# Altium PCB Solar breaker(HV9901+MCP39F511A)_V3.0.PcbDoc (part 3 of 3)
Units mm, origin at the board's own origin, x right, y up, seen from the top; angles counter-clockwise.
Board outline 92.89 x 56.75 mm, 4 copper layers (Component Side, Layer 2, Layer 3, Solder Side), stack 0.466 mm thick; 133 components, 95 nets, 366 pads, 141 vias.
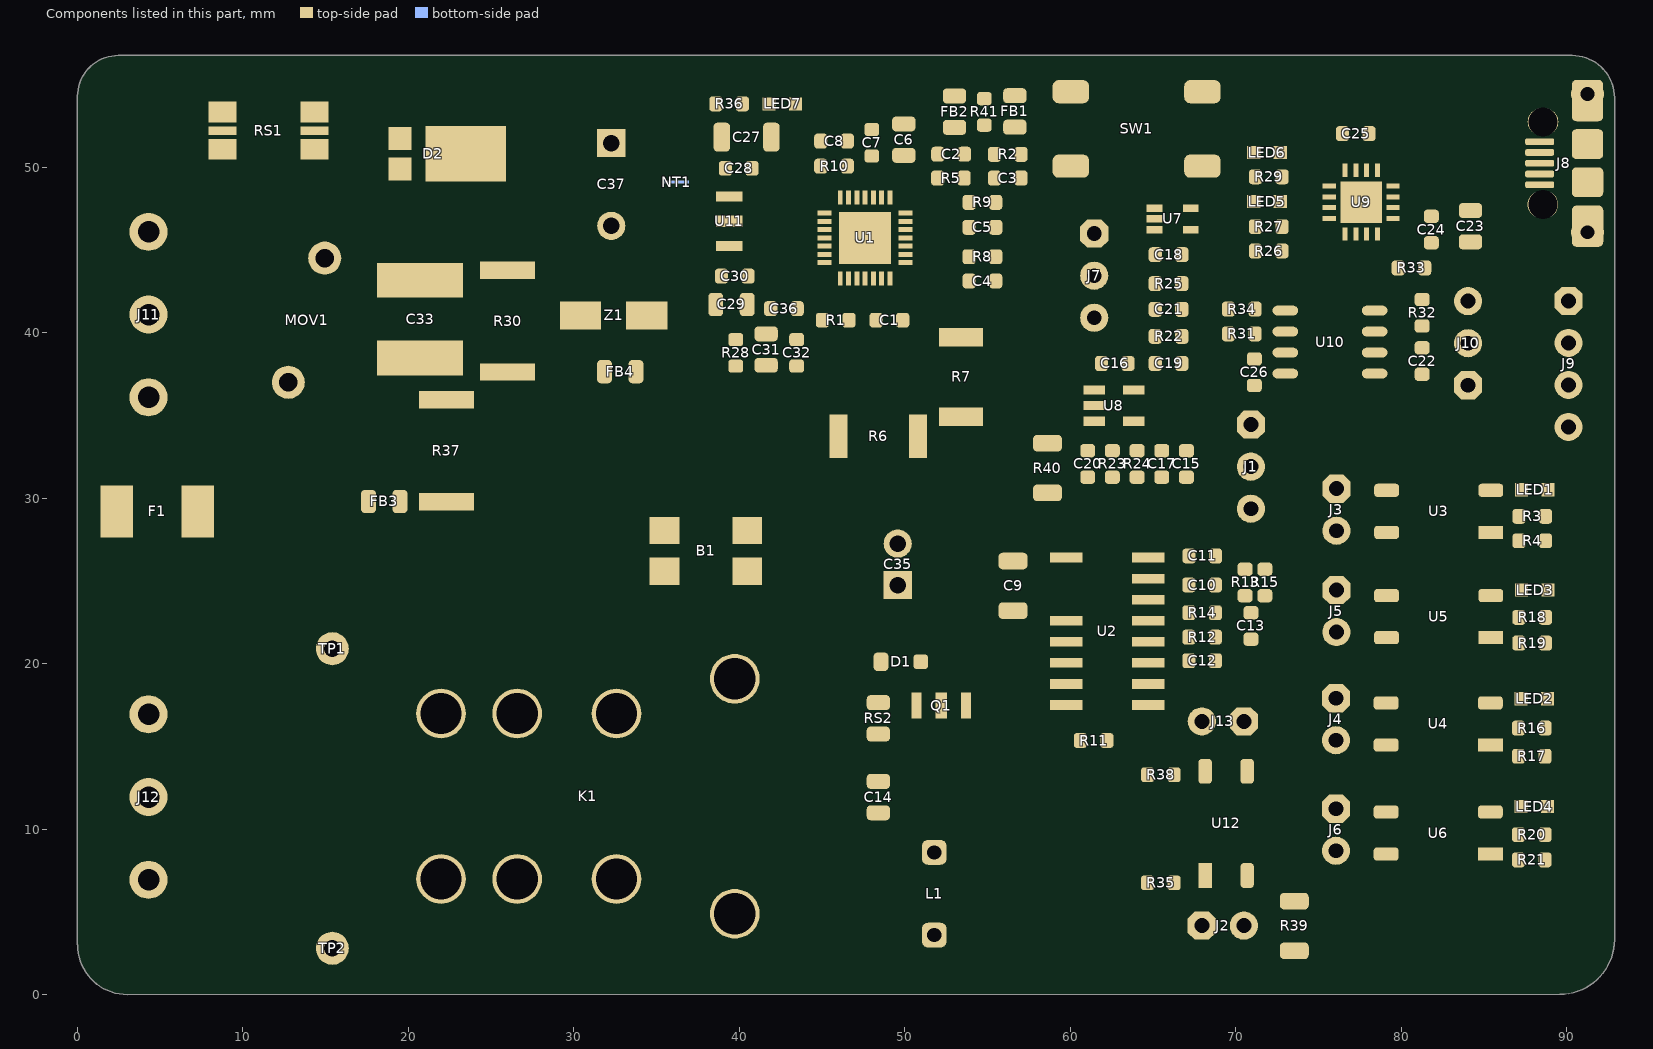
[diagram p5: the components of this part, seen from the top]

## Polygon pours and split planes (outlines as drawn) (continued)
no net on Component Side "Component Side-No Net 3" (solid, pour order 742): 63.218,36.367
no net on Component Side "Component Side-No Net 1" (solid, pour order 722): 32.829,26.67
no net on Component Side "Component Side-No Net 2" (solid, pour order 712): 378.551,40.248
no net on Component Side "NETC3_2" (solid, pour order 690): 42.118,41.086
no net on Component Side "NETC3_2" (solid, pour order 658): 41.407,41.975
no net on Component Side "NETC3_2" (solid, pour order 656): 378.277,41.492
no net on Component Side "NETC3_2" (solid, pour order 650): 378.696,36.505
no net on Component Side "NETC3_2" (solid, pour order 646): 40.342,50.156
no net on Component Side "NETC3_2" (solid, pour order 634): 100.296,19.691
no net on Component Side "NETC3_2" (solid, pour order 628): 46.498,53.28
no net on Component Side "NETC3_2" (solid, pour order 596): 142.359,506.147
GND on Component Side "Component Side-No Net" (solid, shelved, pour order 396): 31.428,9.803 31.428,2.717 31.758,2.387 35.72,2.387 35.72,5.714 36.33,6.324 36.33,8.837 33.789,11.378 31.91,11.378
GND on Solder Side "Solder Side-GND 1" (solid, pour order 1118): 52.286,27.992 8.871,27.992 6.453,25.575 6.453,2.447 8.2,0.7 60,0.7 60.9,1.6 60.9,10.471 60.7,10.671 53.7,17.671 53.7,24 53.7,26.847
GNDB on Solder Side "Solder Side-GNDB" (solid, pour order 998): 73.685,28.829 73.685,7.874 75.133,6.426 75.133,6.325 75.286,6.172 75.286,1.369 75.365,1.369 76.073,0.66 90.576,0.66 90.983,0.254 90.983,0.305 92.329,1.651 92.329,31.496 91.364,32.461 90.5,32.461 90.348,32.614 81.382,32.614 75.641,38.354 75.641,42.266 73.787,44.12 70.751,44.12 70.129,44.741 70.129,48.032 69.546,48.616 59.106,48.616 57.988,47.498 57.988,37.347 52.544,31.902 41.845,31.902 40.132,33.616 40.132,36.678 36.017,40.792 36.017,54 36.017,55.245 35.027,56.236 23.002,56.236 1.778,56.236 0.432,54.889 0.432,44.78 1.302,43.91 6.179,43.91 8.458,41.631 15.496,41.631 25.324,31.799 28.98,28.143 53.391,28.143 53.873,28.626 55.042,29.794 56.439,29.794 56.836,30.191 56.836,31.588 57.15,31.902 60.249,31.902 60.554,31.598 60.554,30.353 61.163,29.743 67.589,29.743 68.438,29.743 69.509,30.814 69.509,35.092 70.129,35.712 71.679,35.712 72.309,35.082 72.309,30.205
GND on Solder Side "Solder Side-GND" (solid, pour order 1004): 61.951,2.438 64.151,0.238 71.987,0.238 73.206,1.458 73.206,28.849 72.566,29.489 71.986,30.069 71.986,32.595 71.536,33.045 70.18,33.045 69.774,32.639 69.774,30.632 68.631,29.489 55.27,29.489 54.116,28.335 54.116,19.671 61.951,11.836
no net on Solder Side "Solder Side-No Net 1" (solid, pour order 1002): 65.405,26.556
AGND on Solder Side "Solder Side-No Net 2" (solid, pour order 990): 36.292,55.26 36.292,41.204 40.335,37.16 40.335,33.744 42.03,32.05 52.319,32.05 57.725,37.455 57.725,47.83 58.708,48.813 69.084,48.813 69.85,49.579 69.85,55.27 68.885,56.236 56.109,56.236 37.336,56.236
GND-ISO on Solder Side "Solder Side-GND_ISO" (solid, pour order 788): 70.364,54.971 70.364,44.887 70.892,44.359 74.59,44.359 76.192,42.756 76.192,38.565 81.616,33.142 91.079,33.142 92.38,34.442 92.38,55.321 91.334,56.367 71.76,56.367
no net on Solder Side "Solder Side-No Net" (solid, pour order 896): 64.11,31.242
no net on Solder Side "NETC3_2" (solid, pour order 492): 107.242,25.462
no net on Solder Side "NETC3_2" (solid, pour order 473): 1034.966,-477.941
GNDB on Layer 2 "Layer 2-GNDB" (solid, pour order 982): 0.561,28.014 0.561,54.766 2.157,56.363 68.504,56.363 69.817,55.049 69.817,44.788 70.663,43.942 74.217,43.942 74.413,43.746 75.438,42.721 75.438,38.862 81.509,32.791 91.434,32.791 92.405,31.82 92.405,2.565 90.678,0.838 89.916,0.838 75.59,0.838 75.006,1.422 75.006,6.528 72.873,8.661 72.873,34.703 72.523,35.052 71.406,36.17 69.817,36.17 68.707,35.059 68.707,31.609 68.707,31.267 68.097,30.658 60.722,30.658 60.477,30.902 60.477,31.532 60.051,31.959 35.666,31.959 30.834,27.127 1.448,27.127
GND on Layer 2 "Layer 2-GND" (solid, pour order 980): 72.509,0.991 74.27,0.991 74.608,1.329 74.608,6.347 72.509,8.445 72.509,34.56 71.057,36.011 69.954,36.011 68.936,34.993 68.936,31.115 68.301,30.48 60.586,30.48 60.3,30.766 60.3,31.416 60.016,31.699 59.367,31.699 45.248,31.699 36.337,31.699 31.434,26.797 0.787,26.797 0.483,26.492 0.483,19.558 0.483,2.53 2.022,0.991
GND-ISO on Layer 2 "Layer 2-GND_ISO" (solid, pour order 748): 72.087,56.693 91.389,56.693 92.862,55.22 92.862,34.925 91.084,33.147 81.902,33.147 76.192,38.856 76.192,42.744 74.562,44.374 70.876,44.374 70.364,44.887 70.387,54.996
5VUSB on Layer 3 "Layer 3-5VUSB" (solid, pour order 1128): 72.729,45.06 73.5,44.289 73.5,42.41 80.71,35.2 81.32,35.2 81.66,35.54 81.66,37.412 80.285,38.787 79.428,38.787 78.1,40.115 78.1,44.272 78.805,44.977 85.099,44.977 87.782,42.293 89.105,40.971 91.378,40.971 92.604,42.197 92.604,54.741 91.211,56.134 71.552,56.134 70.434,55.016 70.434,47.355
3.3D on Layer 3 "Layer 3-3.3D" (solid, pour order 1124): 48.596,52.798 49.324,52.07 52.68,52.07 54.026,53.416 59.974,53.416 66.497,46.893 66.497,44.238 66.889,43.846 67.047,43.688 68.074,43.688 68.402,43.36 68.402,43.043 68.955,42.49 68.955,41.904 68.861,41.81 66.067,41.81 64.353,40.096 63.455,40.096 63.424,40.065 62.738,39.379 62.738,38.955 62.905,38.787 64.083,38.787 64.235,38.787 65.225,39.776 67.589,39.776 68.343,40.53 68.956,40.53 69.236,40.249 69.236,37.651 69.587,37.3 71.28,37.3 71.9,37.92 71.9,41.491 69.933,43.458 69.933,44.977 60.528,54.382 49.454,54.381 49.149,54.077 48.596,53.523
no net on Layer 3 "Layer 3-No Net 1" (solid, pour order 1120): 69.256,40.229
N-IN on Layer 3 "Layer 3-N-IN" (solid, pour order 1116): 14.025,45.714 15.831,45.714 34.4,27.145 34.4,18.881 34.4,15.932 33.8,15.332 31.059,15.332 30.9,15.49 30.379,16.012 30.379,25.921 13.3,43 13.3,44.989
Neutral on Layer 3 "Layer 3-Neutral" (solid, pour order 1114): 2.1,45.742 2.1,48.1 3.9,49.9 18.449,49.9 29.649,38.7 30.6,38.7 31.1,38.2 31.1,37.022 30.577,36.499 30.1,36.499 27.681,36.499 17.012,47.168 7.502,47.168 5.135,44.801 3.048,44.826
L-IN on Layer 3 "Layer 3-L-IN" (solid, pour order 1098): 34.6,4.766 34.6,10.1 31.169,13.531 14.469,13.531 12,16 12,23.761 14.439,26.2 14.439,38.079 13.717,38.8 11.9,38.8 10.769,37.67 10.769,28.231 8.769,26.23 8.769,13.531 11.9,10.4 29.1,10.4 30.6,8.9 30.6,4.728 31.734,3.594 33.428,3.594
GNDB on Layer 3 "Layer 3-GNDB 2" (solid, pour order 1006): 19.554,56.236 36.322,56.236 37.541,55.016 37.541,45.21 37.89,44.861 39.406,43.345 39.406,40.02 39.726,39.7 40.716,39.7 41.021,40.005 41.021,41.833 41.352,42.164 46.329,42.164 47.954,40.539 50.521,40.548 50.81,40.259 51.308,40.259 55.013,40.259 59.28,35.992 60.833,35.992 63.678,33.147 67.986,33.147 68.351,32.782 68.351,17.043 68.351,16.332 67.589,15.57 65.587,15.57 64.541,15.57 63.602,14.63 63.602,11.455 64.084,10.973 70.993,10.973 72.238,12.217 74.168,14.148 74.168,18.212 74.168,31.086 75.071,31.973 76.226,31.952 78.377,29.802 79.35,28.829 79.35,26.304 79.35,21.971 86.97,14.351 86.97,9.931 86.97,7.944 88.361,6.553 88.951,6.553 89.189,6.792 89.189,7.839 88.036,8.992 88.036,14.503 82.728,19.812 82.728,26.682 82.728,35.989 78.392,40.325 78.392,43.038 79.753,44.399 84.099,44.399 87.224,41.275 92.507,35.992 92.507,16.739 92.507,2.948 90.22,0.66 82.321,0.66 57.48,0.66 55.88,2.261 55.88,15.037 59.741,18.898 59.741,30.658 59.563,30.836 58.425,31.973 38.855,31.973 35.558,35.27 18.343,52.411 18.332,55.008
3.3D on Layer 3 "Layer 3-3.3D 1" (solid, pour order 1008): 39.675,40.313 39.675,43.612 37.981,45.306 37.981,53.348 39.522,54.889 45.441,54.889 47.12,53.21 47.12,52.632 46.66,52.172 46.152,52.172 44.856,53.467 40.742,53.467 39.522,52.248 39.522,45.801 40.843,44.48 40.843,43.891 40.844,41.046 40.844,40.189 40.609,39.954 40.034,39.954
GNDB on Layer 3 "Layer 3-GNDB" (solid, pour order 950): 39.776,45.796 39.776,52.121 40.754,53.099 44.884,53.099 45.745,52.237 45.745,50.8 43.536,48.59 43.536,47.818 43.536,47.473 42.774,46.711 42.774,44.78 42.227,44.234 41.339,44.234
GNDB on Layer 3 "Layer 3-GNDB 1" (solid, pour order 946): 46.025,47.396 49.225,47.396 49.225,44.12 46.66,44.12 46.025,44.755
VCC on Layer 3 "Layer 3-VCC" (solid, pour order 922): 73.431,14.529 73.431,33.609 71.633,35.408 70.155,35.408 68.936,34.188 68.936,28.081 68.936,15.702 68.271,15.037 64.578,15.037 64.045,14.596 64.045,11.703 64.255,11.493 64.445,11.303 67.702,11.303 70.206,11.303
no net on Layer 3 "Layer 3-No Net" (solid, pour order 820): 27.305,39.141

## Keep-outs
Keep-Out Layer:
  text ".Layer_Name" at 290.002,-112.792 h1.5

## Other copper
Layer 3:
  pour cut-out: 39.141,1.829

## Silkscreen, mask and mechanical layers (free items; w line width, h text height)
Top Overlay:
  circle w0.381: c78.454,36.5 r0.203
  lines w0.203: 36.623,53.85 36.626,52.539 ; 36.627,52.539 37.973,52.542 ; 37.973,52.959 37.981,49.393 ; 43.84,50.075 44.196,50.075 ; 49.2,54.915 51.638,54.915 51.638,51.714 ; 51.246,51.634 57.731,51.634 ; 51.263,48.587 57.721,48.556 ; 58.877,52.426 60.554,52.4 ; 64.222,41.338 64.516,41.338 ; 67.397,39.785 67.691,39.785 ; 44.454,53.438 44.454,56.308 49.2,56.308 49.2,53.438 44.454,53.438
  lines w0.254: 51.232,48.587 51.246,51.635 ; 57.722,48.641 57.725,49.288 ; 57.731,51.634 57.731,50.584 57.725,49.288 ; 60.423,5.081 60.423,7.418 ; 60.561,7.418 63.249,7.418 ; 66.407,27.458 66.369,19.427 72.668,19.397 72.706,27.434 ; 66.45,27.457 72.706,27.457 ; 67.361,1.295 68.072,1.295 68.072,2.718 ; 69.844,19.411 69.844,20.752 72.669,20.752 ; 70.561,2.667 70.561,1.295 71.317,1.295 ; 73.334,52.095 73.354,56.337 ; 73.508,53.795 73.926,53.793 73.882,44.558 ; 87.138,34.443 87.151,33.745 ; 87.154,33.745 88.621,33.745 ; 57.725,49.288 57.725,49.288 ; 57.059,4.934 57.059,13.514 63.356,13.514 63.356,4.934 57.059,4.934
  text "RESET" at 61.7,55.6 h1.4
  text "Inlet" at 1.981,52.268 h3.05
  text "1" at 63.068,45.695 h1.52
  text "TEMP OUT" at 57.556,45.212 h0.89
  text "N" at 8.636,45.11 h2.54
  text "ANALOG /          _IN" at 56.464,42.443 h0.89
  text "1" at 91.872,41.465 h1.52
  text "PWM" at 57.81,40.488 h0.89
  text "G" at 8.509,40.386 h2.54
  text "1" at 81.763,36.017 h1.52
  text "L" at 8.636,35.219 h2.54
  text "Ext.isolated / serial comm" at 88.316,34.747 h1.52 r90
  text "VCC" at 69.118,33.833 h1.4 r90
  text "" at 33,32.2 h8.89
  text "1" at 77.775,30.912 h1.52
  text "GND" at 69.063,30.861 h1.4 r90
  text "*h" at 25.414,29.277 h4.57
  text "-" at 39.7,29.05 h1
  text "EVENT1" at 74.346,28.902 h1.52 r90
  text "VDD" at 69.037,27.911 h1.4 r90
  text "Fast Blow" at 1.93,25.832 h1.52
  text "1" at 77.775,24.816 h1.52
  text "Solar breaker(HV9901+ / MCP39F511A)  V3.0" at 10.3,24.7 h2.16
  text "250VAC,1A" at 1.245,24.409 h1.52
  text "+" at 39.7,23.425 h1
  text "2020.6.19" at 23.1,23.3 h1.78
  text "ZCD" at 74.346,23.076 h1.52 r90
  text "K1-PIN3" at 8.7,21.2 h1.52
  text "A" at 71.095,19.634 h1.4
  text "5" at 31.9,19.2 h2.54
  text "1" at 21.386,19.172 h2.54
  text "3" at 25.8,19.172 h2.54
  text "1" at 77.775,18.39 h1.52
  text "ENI" at 67.056,18.212 h1.27
  text "GND" at 69.317,18.212 h1.27
  text "N" at 8.636,16.002 h2.54
  text "7" at 39.306,15.353 h2.54
  text "EVENT2" at 74.346,14.224 h1.52 r90
  text "1" at 77.775,11.735 h1.52
  text "G" at 8.509,10.922 h2.54
  text "8" at 39.1,7.112 h2.54
  text "PWM Output" at 74.295,6.553 h1.4 r90
  text "L" at 8.636,6.35 h2.54
  text "A" at 61.293,5.666 h1.78
  text "C" at 83.21,3.378 h3.81
  text "2" at 21.2,3.3 h2.54
  text "4" at 25.9,3.3 h2.54
  text "6" at 32.1,3.3 h2.54
  text "" at 80.442,3.124 h3.81
  text "" at 77.009,2.819 h3.81
  text "" at 86.919,2.388 h3.81
  text "" at 89.56,2.21 h3.81
  text "Outlet" at 1.168,1.651 h3.05
  text "EXT-MCU-IN" at 60.071,0.94 h1.27
  text "GND-EXT-MCU" at 71.552,0.94 h1.27
  text "K1-PIN4" at 9.4,0.8 h1.52
Top Paste:
  text ".ProjectRevisionART" at 325.18,-112.615 h1.5
  text ".Layer_Name" at 290.002,-112.792 h1.5
Bottom Paste:
  text ".ProjectRevisionART" at 325.18,-112.615 h1.5
  text ".Layer_Name" at 290.002,-112.792 h1.5
NOTES (M1):
  lines w0.051: 36.751,12.112 ccw(c36.795,12.232) 36.795,12.104 ; 37.538,56.877 cw(c37.543,56.75) 37.543,56.877 cw(c37.543,54.191) 37.564,56.877 ; 37.564,56.877 cw(c37.543,54.191) 37.574,56.877 ; 37.564,56.877 37.574,56.877 ; 37.564,56.877 37.569,56.877 cw(c37.569,56.75) 37.574,56.877
  lines w0.254: -0.232,61.746 -0.232,62.254 ; 2.768,61 -0.232,62 ; 2.768,63 -0.232,62 ; 34.559,62 -0.232,62 ; 57.864,62 92.655,62 ; 89.655,61 92.655,62 ; 89.655,63 92.655,62 ; 92.655,61.746 92.655,62.254 ; 99,3.021 100,0.021 ; 99,53.753 100,56.753 ; 99.746,0.021 100.254,0.021 ; 99.746,56.753 100.254,56.753 ; 100,16.734 100,0.021 ; 100,40.04 100,56.753 ; 101,3.021 100,0.021 ; 101,53.753 100,56.753
  text "92.886mm" at 34.813,60.348 h3
  text "56.733mm" at 101.652,16.988 h3 r90
  text ".Layer_Name" at 308.002,-112.792 h1.5
Route Tool Path:
  lines w0.254: 0,3.001 0,54.282 cw(c2.471,54.282) 2.471,56.752 ; 0.012,3.001 ccw(c3.013,3.001) 3.013,0 ; 2.547,56.75 90.404,56.75 ; 3.013,-0.001 89.58,0.011 ; 89.58,0.021 ccw(c89.58,3.327) 92.886,3.327 92.886,54.191 ccw(c90.328,54.191) 90.328,56.75
REF POINTS (M3):
  text ".Layer_Name" at 290.002,-112.792 h1.5
FAB (M4):
  lines w0.254: 249.419,73.357 251.959,75.897 ; 249.419,75.897 251.959,73.357 ; 320.158,58.934 321.682,58.934 ; 320.158,60.458 321.682,60.458 ; 320.92,59.696 320.92,61.22 ; 248.784,31.892 248.784,35.702 252.594,35.702 252.594,31.892 248.784,31.892 ; 248.784,37.502 252.594,37.502 252.594,41.312 248.784,41.312 248.784,37.502 ; 248.784,43.002 248.784,46.812 252.594,46.812 252.594,43.002 248.784,43.002 ; 248.784,48.282 252.594,48.282 252.594,52.092 248.784,52.092 248.784,48.282 ; 248.784,72.722 252.594,72.722 252.594,76.532 248.784,76.532 248.784,72.722 ; 259.024,-2.248 278.475,-2.248 278.475,1.562 259.024,1.562 259.024,-2.248 ; 269.104,23.152 269.104,26.962 332.604,26.962 332.604,23.152 269.104,23.152 ; 276.724,72.722 276.724,76.532 280.534,76.532 280.534,72.722 276.724,72.722 ; 279.264,10.452 279.264,14.262 332.604,14.262 332.604,10.452 279.264,10.452 ; 279.264,16.802 332.604,16.802 332.604,20.612 279.264,20.612 279.264,16.802 ; 299.475,53.282 299.475,57.092 303.285,57.092 303.285,53.282 299.475,53.282 ; 299.584,58.172 299.584,61.982 308.474,61.982 308.474,58.172 299.584,58.172 ; 299.584,63.022 299.584,66.832 308.474,66.832 308.474,63.022 299.584,63.022 ; 299.584,67.872 308.474,67.872 308.474,71.682 299.584,71.682 299.584,67.872 ; 299.584,72.722 299.584,76.532 303.394,76.532 303.394,72.722 299.584,72.722 ; 308.314,-2.248 308.314,1.562 325.475,1.562 325.475,-2.248 308.314,-2.248 ; 316.475,53.282 320.285,53.282 320.285,57.092 316.475,57.092 316.475,53.282 ; 322.444,58.172 331.334,58.172 331.334,61.982 322.444,61.982 322.444,58.172
  text "THIS PCB TO BE MANUFACTURED TO MEET ALL ACCEPTANCE LEVELS" at 228.464,86.518 h1.78
  text "OF A CLASS 2 PCB PER ANSI/IPC-A-600G." at 228.464,82.708 h1.78
  text "MATERIAL:" at 228.464,78.088 h1.78
  text "FR-4 or Equivalent" at 248.784,78.088 h1.78
  text "FINISH:" at 236.514,75.897 h1.78
  text "CONTROLLED IMPEDANCE" at 304.975,73.856 h1.78
  text "MULTILAYER" at 254.499,73.738 h1.78
  text "4" at 277.994,73.738 h1.78
  text "LAYERS" at 282.439,73.738 h1.78
  text "Cu WEIGHT EXTERNAL LAYERS" at 248.784,68.888 h1.78
  text "50um" at 300.854,68.888 h1.78
  text "FINISHED" at 310.379,68.888 h1.78
  text "Cu WEIGHT INTERNAL LAYERS" at 248.784,64.038 h1.78
  text "35um" at 300.854,64.038 h1.78
  text "FINISHED" at 310.379,64.038 h1.78
  text "FINISHED OVERALL THICKNESS" at 248.784,59.188 h1.78
  text "1.6" at 302.124,59.188 h1.78
  text "mm" at 310.379,59.188 h1.78
  text "10" at 324.984,59.188 h1.78
  text "%" at 333.239,59.188 h1.78
  text "COPPER THIEVING ALLOWED" at 248.975,54.356 h1.78
  text "YES" at 305.975,54.356 h1.78
  text "NO" at 322.975,54.356 h1.78
  text "X" at 317.566,53.856 h2.6
  text "LEAD-FREE HOT AIR LEVELING" at 254.475,49.556 h1.78
  text "X" at 249.875,48.856 h2.6
  text "IMMERSION GOLD" at 254.499,44.018 h1.78
  text "IMMERSION TIN" at 254.499,38.518 h1.78
  text "SMOBC WITH SELECTIVE GOLD PLATING ON LANDS" at 254.499,34.813 h1.78
  text "INDICATED. 1um GOLD OVER 5-10 um NICKEL" at 254.499,31.003 h1.78
  text "SOLDERMASK" at 248.784,24.168 h1.78
  text "DYNACHEM EPIC 200 LPI OR EQUIVALENT" at 270.374,24.168 h1.78
  text "SOLDERMASK COLOR" at 248.784,17.818 h1.78
  text "GREEN HIGH GLOSS" at 280.534,17.818 h1.78
  text "SILKSCREEN COLOR" at 248.784,11.468 h1.78
  text "WHITE" at 280.534,11.468 h1.78
  text "ALL HOLES TO BE LOCATED BY THE COORDINATES FROM THE NC DRILL DATA PROVIDED." at 228.464,5.118 h1.78
  text "05-" at 260.475,-1.144 h1.78
  text ".ProjectBoardNumber" at 265.475,-1.144 h1.78
  text "PCB REV" at 296.475,-1.144 h1.78
  text "USE ARTWORK SET NO." at 228.464,-1.232 h1.78
  text ".ProjectRevisionART" at 309.625,-1.394 h1.78
  text "ALL UL LOGO, MANUFACTURER'S ID, AND DATE CODES SHALL BE PLACED" at 228.464,-7.582 h1.78
  text "ON THE BOTTOM SIDE UNLESS OTHERWISE INDICATED." at 228.464,-11.392 h1.78
  text "ANY ALTERNATIVES TO THE ABOVE SPECIFICATIONS MUST FIRST BE APPROVED." at 227.975,-16.644 h1.78
  text ".ProjectRevisionFAB" at 325.18,-112.615 h1.5
  text ".Layer_Name" at 290.002,-112.792 h1.5
Case (M5):
  text ".Layer_Name" at 290.002,-112.792 h1.5
Cover (M6):
  text ".Layer_Name" at 290.002,-112.792 h1.5
Terminal Block (M7):
  text ".Layer_Name" at 290.002,-112.792 h1.5
Milling (M8):
  text ".Layer_Name" at 290.002,-112.792 h1.5
V-Cut (M9):
  text ".Layer_Name" at 290.002,-112.792 h1.5
Assy BOT (M10):
  text ".variantName" at 39.572,-96.792 h0.9
  text "ASSEMBLY VARIANT:" at 53.822,-96.792 h0.9
  text "DOCUMENT NUMBER:" at 7.552,-105.042 h1.14
  text "-D" at -6.448,-108.042 h1.78
  text ".ProjectBoardNumber" at 1.802,-108.042 h1.78
  text "02-" at 7.302,-108.042 h1.78
  text ".ProjectRevisionASSY" at -9.375,-112.615 h1.5
  text ".Layer_Name" at 25.502,-112.792 h1.5
Assy TOP (M11):
  text "ASSEMBLY NOTES:" at -5.948,-63.286 h4
  text "1. ALL COMPONENTS SHALL BE RoHS COMPLIANT." at -15.198,-68.242 h3
  text "2. ALL UNUSED THROUGH HOLE COMPONENT LOCATIONS SHALL BE FREE OF SOLDER." at -15.198,-71.242 h3
  text "3. ALL COMPONENTS SHALL BE MOUNTED FLUSH TO THE BOARD, EXCEPT AS NOTED." at -15.198,-74.242 h3
  text "4. FINISHED BOARD SHALL BE FREE OF ALL RESIDUES." at -15.198,-77.242 h3
  text "5. ALL LEADS SHALL BE TRIMMED TO A MAXIMUM HEIGHT OF 2mm" at -15.198,-80.242 h3
  text "6. PLACE LABEL  ON THE LOCATION INDICATED." at -15.198,-83.242 h3
  text "7." at -15.198,-86.242 h3
3D BOT (M12):
  text ".Layer_Name" at 290.002,-112.792 h1.5
3D TOP (M13):
  text ".Layer_Name" at 290.002,-112.792 h1.5
TITLE (M16):
  lines w0.1: 261.502,-95.542 343.322,-95.542 ; 318.502,-88.042 318.502,-91.042 343.322,-91.042 ; 332.042,-112.677 332.042,-111.407 ; 332.042,-112.042 342.202,-112.042 ; 332.202,-110.842 332.202,-109.842 ; 332.202,-110.342 342.202,-110.342 ; 334.582,-112.677 334.582,-111.407 ; 337.122,-112.677 337.122,-111.407 ; 337.202,-110.642 337.202,-110.042 ; 339.662,-112.677 339.662,-111.407 ; 342.202,-112.677 342.202,-111.407 ; 342.202,-110.842 342.202,-109.842 ; 343.322,-91.042 343.322,-91.042
  lines w0.127: -32.598,-58.217 -27.518,-58.217 ; -32.598,62.433 -27.518,62.433 ; -32.443,9.839 -27.363,9.839 ; 30.902,-118.542 30.902,-113.462 ; 94.402,-118.542 94.402,-113.462 ; 157.902,-118.542 157.902,-113.462 ; 157.902,117.678 157.902,122.758 ; 193.462,-113.462 229.022,-113.462 ; 221.402,-118.542 221.402,-113.462 ; 221.402,117.678 221.402,122.758 ; 227.502,-113.462 227.502,-88.042 343.322,-88.042 ; 261.502,-113.462 261.502,-88.042 ; 261.502,-109.042 343.322,-109.042 ; 261.502,-103.042 343.322,-103.042 ; 261.502,-97.042 343.322,-97.042 ; 284.902,-118.542 284.902,-113.462 ; 284.902,117.678 284.902,122.758 ; 289.502,-113.462 289.502,-97.042 ; 307.502,-109.042 307.502,-103.042 ; 320.502,-113.462 320.502,-109.042 ; 328.002,-113.462 328.002,-103.042 ; 343.322,-82.982 343.322,-113.462 ; 343.322,-58.217 348.402,-58.217 ; 343.322,2.108 348.402,2.108 ; 343.322,-113.462 343.322,117.678 -27.518,117.678 -27.518,-113.462 343.322,-113.462 ; -32.598,-118.542 -32.598,122.758 348.402,122.758 348.402,-118.542 -32.598,-118.542
  lines w0.305: 221.502,117.458 221.502,112.958 ; 232.502,108.458 232.502,112.958 232.502,117.458 ; 245.002,108.458 245.002,112.958 245.002,117.458 ; 323.502,108.458 323.502,112.958 323.502,117.458 ; 343.002,108.458 221.502,108.458 221.502,112.958 ; 343.002,112.958 221.502,112.958
  text "4" at 188.967,119.456 h1.78
  text "5" at 252.441,119.456 h1.78
  text "6" at 316.068,119.456 h1.78
  text "REV" at 224.002,114.458 h0.76
  text "ECO" at 234.002,114.458 h0.76
  text "Comments" at 280.502,113.958 h0.76
  text "Date" at 328.502,113.958 h0.76
  text "A" at -31.089,98.622 h1.78
  text "A" at 345.227,90.424 h1.78
  text "B" at -30.693,29.972 h1.78
  text "B" at 345.227,29.972 h1.78
  text "C" at -30.693,-30.353 h1.78
  text "C" at 345.227,-30.353 h1.78
  text "PART NUMBER:" at 319.502,-90.042 h1
  text ".ProjectpartNumber" at 331.502,-90.292 h1.5
  text "TITLE:" at 262.502,-90.542 h1.14
  text "D" at -30.693,-90.551 h1.78
  text "D" at 345.227,-90.551 h1.78
  text ".ProjectTitle" at 262.502,-94.542 h2.5
  text "PCB DESIGNER:" at 262.502,-99.042 h1.14
  text "GERBER FILE:" at 290.502,-99.042 h1.14
  text ".ProjectDrawnBy" at 262.502,-102.042 h1.78
  text ".Plot_File_Name" at 290.502,-102.042 h1.5
  text "M" at 230.502,-104.042 h15.24
  text "ENGINEER:" at 262.502,-105.042 h1.14
  text "BOARD NUMBER:" at 290.502,-105.042 h1.14
  text "DATE:" at 329.202,-105.042 h1.14
  text "Microchip Technology Inc." at 229.272,-107.302 h1.78
  text ".ProjectBoardNumber" at 295.245,-108.017 h1.78
  text ".ProjectEngineer" at 262.502,-108.042 h1.78
  text "04-" at 290.502,-108.042 h1.78
  text ".PRINT_DATE" at 329.202,-108.042 h1.5
  text "2355 W. Chandler Blvd." at 230.502,-110.042 h1.78
  text "LAYER NAME:" at 290.502,-110.542 h1.14
  text "10mm" at 328.502,-110.642 h0.7
  text "PCB FILE NAME:" at 262.502,-110.792 h1.14
  text "REV:" at 321.252,-110.792 h1.14
  text "400mil" at 328.402,-112.342 h0.7
  text "Chandler, AZ  85224" at 231.502,-112.542 h1.78
  text ".PCB_FILE_NAME_NO_PATH" at 262.502,-112.792 h1.14
  text "1" at -1.322,-116.764 h1.78
  text "2" at 62.068,-116.764 h1.78
  text "3" at 125.298,-116.764 h1.78
  text "4" at 188.967,-116.764 h1.78
  text "5" at 252.441,-116.764 h1.78
  text "6" at 316.068,-116.764 h1.78
Drill Drawing:
  circle w0.254: c114.048,-88.639 r0.21
  circle w0.254: c114.048,-88.639 r0.35
  circle w0.254: c114.048,-90.215 r0.35
  lines w0.254: 113.697,-96.869 114.398,-96.869 114.398,-96.169 113.697,-96.169 113.697,-96.869 ; 113.697,-95.293 114.048,-95.118 114.398,-95.293 114.223,-94.943 114.398,-94.593 114.048,-94.768 113.697,-94.593 113.873,-94.943 113.697,-95.293 ; 113.697,-93.542 113.873,-93.542 113.873,-93.717 114.223,-93.717 114.223,-93.542 114.398,-93.542 114.398,-93.192 114.223,-93.192 114.223,-93.017 113.873,-93.017 113.873,-93.192 113.697,-93.192 113.697,-93.542 ; 113.697,-91.966 113.873,-91.966 113.873,-92.141 114.223,-92.141 114.223,-91.966 114.398,-91.966 114.398,-91.616 114.223,-91.616 114.223,-91.44 113.873,-91.44 113.873,-91.616 113.697,-91.616 113.697,-91.966 ; 113.697,-86.712 114.398,-86.712 114.048,-87.413 113.697,-86.712 ; 113.697,-85.837 113.697,-85.662 113.873,-85.486 113.697,-85.311 113.697,-85.136 113.873,-85.136 114.048,-85.311 114.223,-85.136 114.398,-85.136 114.398,-85.311 114.223,-85.486 114.398,-85.662 114.398,-85.837 114.223,-85.837 114.048,-85.662 113.873,-85.837 113.697,-85.837 ; 113.697,-84.085 113.873,-84.085 114.048,-84.261 114.223,-84.085 114.398,-84.085 114.223,-83.91 114.398,-83.735 114.223,-83.735 114.048,-83.56 113.873,-83.735 113.697,-83.735 113.873,-83.91 113.697,-84.085 ; 113.697,-82.334 114.048,-82.685 114.398,-82.334 114.048,-81.984 113.697,-82.334 ; 113.838,-91.896 113.943,-91.896 113.943,-92.001 114.153,-92.001 114.153,-91.896 114.258,-91.896 114.258,-91.686 114.153,-91.686 114.153,-91.581 113.943,-91.581 113.943,-91.686 113.838,-91.686 113.838,-91.896
  lines w0.381: 113.023,-97.342 137.205,-97.342 ; 113.023,-81.581 137.205,-81.581 ; 117.074,-98.918 117.074,-80.005 ; 121.355,-98.918 121.355,-80.005 ; 129.018,-98.918 129.018,-80.005 ; 132.16,-98.918 132.16,-80.005 ; 113.023,-98.918 137.205,-98.918 137.205,-80.005 113.023,-80.005 113.023,-98.918
  text "Symbol" at 113.968,-81.108 h0.91
  text "Hit Count" at 117.547,-81.108 h0.91
  text "Finished Hole Size" at 121.828,-81.108 h0.91
  text "Plated" at 129.491,-81.108 h0.91
  text "Hole Type" at 132.632,-81.108 h0.91
  text "2" at 117.547,-82.685 h0.76
  text "0.825mm (32.48mil)" at 121.828,-82.685 h0.76
  text "PTH" at 129.491,-82.685 h0.76
  text "Slot" at 132.632,-82.685 h0.76
  text "2" at 117.547,-84.261 h0.76
  text "0.850mm (33.47mil)" at 121.828,-84.261 h0.76
  text "PTH" at 129.491,-84.261 h0.76
  text "Round" at 132.632,-84.261 h0.76
  text "2" at 117.547,-85.837 h0.76
  text "1.100mm (43.31mil)" at 121.828,-85.837 h0.76
  text "PTH" at 129.491,-85.837 h0.76
  text "Round" at 132.632,-85.837 h0.76
  text "2" at 117.547,-87.413 h0.76
  text "1.750mm (68.90mil)" at 121.828,-87.413 h0.76
  text "PTH" at 129.491,-87.413 h0.76
  text "Slot" at 132.632,-87.413 h0.76
  text "4" at 117.547,-88.989 h0.76
  text "0.300mm (11.81mil)" at 121.828,-88.989 h0.76
  text "PTH" at 129.491,-88.989 h0.76
  text "Round" at 132.632,-88.989 h0.76
  text "6" at 117.547,-90.565 h0.76
  text "1.000mm (39.37mil)" at 121.828,-90.565 h0.76
  text "PTH" at 129.491,-90.565 h0.76
  text "Round" at 132.632,-90.565 h0.76
  text "6" at 117.547,-92.141 h0.76
  text "1.300mm (51.18mil)" at 121.828,-92.141 h0.76
  text "PTH" at 129.491,-92.141 h0.76
  text "Round" at 132.632,-92.141 h0.76
  text "8" at 117.547,-93.717 h0.76
  text "2.500mm (98.43mil)" at 121.828,-93.717 h0.76
  text "PTH" at 129.491,-93.717 h0.76
  text "Round" at 132.632,-93.717 h0.76
  text "25" at 117.547,-95.293 h0.76
  text "0.900mm (35.43mil)" at 121.828,-95.293 h0.76
  text "PTH" at 129.491,-95.293 h0.76
  text "Round" at 132.632,-95.293 h0.76
  text "137" at 117.547,-96.869 h0.76
  text "0.305mm (12.00mil)" at 121.828,-96.869 h0.76
  text "PTH" at 129.491,-96.869 h0.76
  text "Round" at 132.632,-96.869 h0.76
  text "194 Total" at 117.547,-98.445 h0.76
  text "Slot definitions :" at 113.968,-99.548 h0.76
  text "Routed Path Length" at 119.154,-99.548 h0.76
  text "= Calculated from tool start centre position to tool end centre position." at 125.579,-99.548 h0.76
  text "Hole Length" at 119.154,-100.179 h0.76
  text "= Routed Path Length + Tool Size = Slot length as defined in the PCB layout" at 123.194,-100.179 h0.76
TITLE MIRROR (M17):
  lines w0.1: -27.498,-95.542 54.322,-95.542 ; -26.398,-112.677 -26.398,-111.407 ; -26.398,-112.042 -16.238,-112.042 ; -26.398,-110.842 -26.398,-109.842 ; -26.398,-110.342 -16.398,-110.342 ; -23.858,-112.677 -23.858,-111.407 ; -21.398,-110.642 -21.398,-110.042 ; -21.318,-112.677 -21.318,-111.407 ; -18.778,-112.677 -18.778,-111.407 ; -16.398,-110.842 -16.398,-109.842 ; -16.238,-112.677 -16.238,-111.407 ; -2.678,-88.042 -2.678,-91.042 -27.498,-91.042 ; -27.498,-91.042 -27.498,-91.042
  lines w0.127: -32.598,-58.217 -27.518,-58.217 ; -32.598,62.433 -27.518,62.433 ; -27.518,-109.042 54.302,-109.042 ; -27.518,-103.042 54.302,-103.042 ; -27.498,-97.042 54.322,-97.042 ; -27.498,-88.042 88.322,-88.042 88.322,-113.462 ; -12.198,-113.462 -12.198,-103.042 ; -4.698,-113.462 -4.698,-109.042 ; 8.302,-109.042 8.302,-103.042 ; 26.322,-113.462 26.322,-97.042 ; 30.902,-118.542 30.902,-113.462 ; 54.322,-113.462 54.322,-88.042 ; 94.402,-118.542 94.402,-113.462 ; 157.902,-118.542 157.902,-113.462 ; 157.902,117.678 157.902,122.758 ; 221.402,-118.542 221.402,-113.462 ; 221.402,117.678 221.402,122.758 ; 284.902,-118.542 284.902,-113.462 ; 284.902,117.678 284.902,122.758 ; 343.322,-58.217 348.402,-58.217 ; 343.322,2.108 348.402,2.108 ; -32.598,-118.542 348.402,-118.542 348.402,122.758 -32.598,122.758 -32.598,-118.542 ; -27.518,-113.462 343.322,-113.462 343.322,117.678 -27.518,117.678 -27.518,-113.462
  text "3" at 190.507,119.456 h1.78
  text "2" at 253.737,119.456 h1.78
  text "1" at 317.126,119.456 h1.78
  text "A" at -29.878,98.614 h1.78
  text "A" at 346.497,90.424 h1.78
  text "B" at -29.423,29.972 h1.78
  text "B" at 346.497,29.972 h1.78
  text "C" at -29.423,-30.353 h1.78
  text "C" at 346.497,-30.353 h1.78
  text "PART NUMBER:" at -3.678,-90.042 h1
  text "TITLE:" at 53.322,-90.042 h1.14
  text ".ProjectpartNumber" at -15.678,-90.292 h1.5
  text "D" at -29.423,-90.551 h1.78
  text "D" at 346.497,-90.551 h1.78
  text ".ProjectTitle" at 53.322,-94.542 h2.5
  text "GERBER FILE:" at 25.322,-99.042 h1.14
  text "PCB DESIGNER:" at 53.322,-99.042 h1.14
  text ".Plot_File_Name" at 25.322,-102.042 h1.5
  text ".ProjectDrawnBy" at 53.322,-102.042 h1.78
  text "M" at 85.322,-104.042 h15.24
  text "DATE:" at -13.398,-105.042 h1.14
  text "BOARD NUMBER:" at 25.302,-105.042 h1.14
  text "ENGINEER:" at 53.302,-105.042 h1.14
  text "Microchip Technology Inc." at 86.552,-107.302 h1.78
  text ".PRINT_DATE" at -13.398,-108.042 h1.5
  text ".ProjectBoardNumber" at 20.302,-108.042 h1.78
  text "04-" at 25.302,-108.042 h1.78
  text ".ProjectEngineer" at 53.302,-108.042 h1.78
  text "2355 W. Chandler Blvd." at 85.322,-110.042 h1.78
  text "LAYER NAME:" at 25.302,-110.542 h1.14
  text "10mm" at -12.698,-110.642 h0.7
  text "REV:" at -5.448,-110.792 h1.14
  text "PCB FILE NAME:" at 53.302,-110.792 h1.14
  text "400mil" at -12.598,-112.342 h0.7
  text "Chandler, AZ  85224" at 84.322,-112.542 h1.78
  text ".PCB_FILE_NAME_NO_PATH" at 53.302,-112.792 h1.14
  text "6" at -0.263,-116.764 h1.78
  text "5" at 63.364,-116.764 h1.78
  text "4" at 126.838,-116.764 h1.78
  text "3" at 190.507,-116.764 h1.78
  text "2" at 253.737,-116.764 h1.78
  text "1" at 317.126,-116.764 h1.78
